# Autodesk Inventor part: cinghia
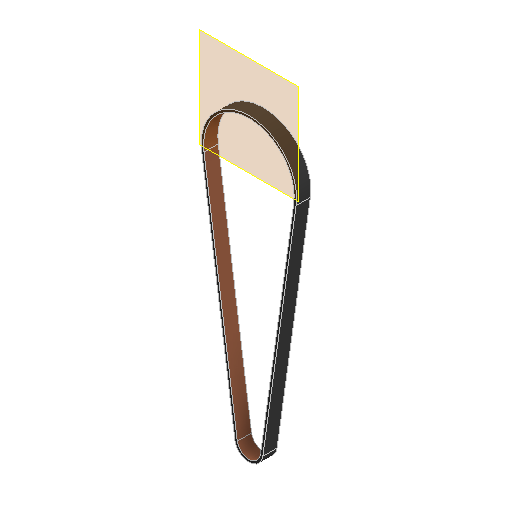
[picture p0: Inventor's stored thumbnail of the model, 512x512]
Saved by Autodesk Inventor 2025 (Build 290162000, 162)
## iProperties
Created: 2025-06
Part Number: cinghia
Material: Gomma, Silicone
Document SubType Name: Modeling
Designer: Ryzen5700u
Density: 1.25 g/cm^3
Appearance: Gomma - Nero
lunghezza: 313,384 mm
Author: Ryzen5700u
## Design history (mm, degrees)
node "Piano di lavoro1"
sketch "Schizzo3"
  geometry: L1 (0, 120)-(0, 20); L2 (-18.81, 22.679)-(-4.851, 120.691); L3 (18.81, 22.679)-(4.851, 120.691); C1 r 5 at (0, 20); C2 r 3 at (0, 120) reference; C3 r 2.5 at (0, 20) reference; A1 r 19 centre (0, 20) between (-18.81, 22.679) and (18.81, 22.679); A2 r 4.9 centre (0, 120) between (4.851, 120.691) and (-4.851, 120.691); 1 further point
  constraints: 6 end point, 4 point on circle, 4 tangent, 3 centre point, 3 coincident, 1 vertical
  dimensions: "d1" = 38 diameter of A1; "d2" = 9.8 diameter of A2
feature "SupEstrusione1" sketch "Schizzo3" dims "d3" = 6, "d4" = 0
feature "Ispessimento1" dims "d5" = 1, "d6" = 1
node "Solido1"
node "Riferimento4"
node "Superf1"
node "Riferimento5"
